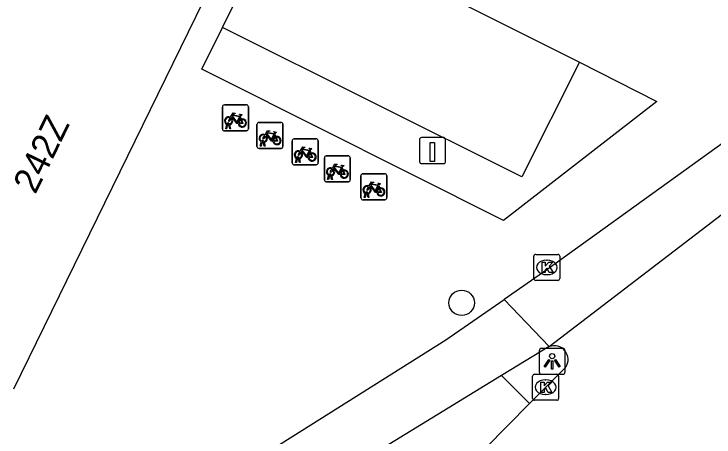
# Model space of a CAD drawing. Extents: x 160107 to 160928, y 382056 to 382918.
# Drawn here: x 160344.92 to 160371.87, y 382084.96 to 382101.23 of the extents above; entities that cross this region are included whole.
import ezdxf

# ---------------------------------------------------------------- set-up
doc = ezdxf.new("R2010")
doc.units = 0
for name, color, linetype in [('IMGEO_Boom', 7, 'Continuous'), ('IMGEO_Fietsenrek', 7, 'Continuous'), ('IMGEO_Fietspad_gesloten', 7, 'Continuous'), ('IMGEO_Kolk', 7, 'Continuous'), ('IMGEO_Laadpaal', 7, 'Continuous'), ('IMGEO_Lichtpunt', 7, 'Continuous'), ('IMGEO_Pand', 7, 'Continuous'), ('IMGEO_Pand_nummerreeks', 7, 'Continuous'), ('IMGEO_Parkeervlak_open', 7, 'Continuous'), ('IMGEO_Rijbaan_lokaal_gesloten', 7, 'Continuous'), ('IMGEO_Verkeerseiland_gesloten', 7, 'Continuous'), ('IMGEO_Voetpad_open', 7, 'Continuous')]:
    doc.layers.add(name, color=color, linetype=linetype)

msp = doc.modelspace()

# ---------------------------------------------------------------- linework, layer by layer
at = {"layer": 'IMGEO_Boom'}
msp.add_circle((160362.153, 382090.119), 0.489, dxfattribs=at)
at = {"layer": 'IMGEO_Fietsenrek'}
for p, q in [((160352.946, 382096.808), (160352.946, 382097.649)), ((160352.946, 382097.649), (160352.946, 382096.808)), ((160353.021, 382097.733), (160353.862, 382097.733)), ((160353.862, 382097.733), (160353.021, 382097.733)), ((160353.946, 382097.658), (160353.946, 382096.817)), ((160353.946, 382096.817), (160353.946, 382097.658)), ((160353.633, 382097.282), (160353.669, 382097.187)), ((160353.073, 382096.817), (160353.112, 382096.977)), ((160353.142, 382096.965), (160353.107, 382096.817)), ((160353.184, 382096.989), (160353.183, 382096.993)), ((160353.225, 382096.817), (160353.191, 382096.959)), ((160353.215, 382097), (160353.216, 382096.993)), ((160353.223, 382096.963), (160353.258, 382096.817)), ((160354.276, 382096.135), (160354.276, 382096.976)), ((160354.276, 382096.976), (160354.276, 382096.135)), ((160354.351, 382097.06), (160355.192, 382097.06)), ((160355.192, 382097.06), (160354.351, 382097.06)), ((160355.276, 382096.985), (160355.276, 382096.144)), ((160355.276, 382096.144), (160355.276, 382096.985)), ((160353.871, 382096.733), (160353.03, 382096.733)), ((160353.03, 382096.733), (160353.871, 382096.733)), ((160353.107, 382096.817), (160353.073, 382096.817)), ((160353.258, 382096.817), (160353.225, 382096.817)), ((160354.963, 382096.609), (160354.999, 382096.514)), ((160354.403, 382096.144), (160354.442, 382096.304)), ((160354.472, 382096.292), (160354.437, 382096.144)), ((160354.514, 382096.316), (160354.513, 382096.32)), ((160354.545, 382096.327), (160354.546, 382096.32)), ((160355.63, 382095.501), (160355.63, 382096.342)), ((160355.63, 382096.342), (160355.63, 382095.501)), ((160355.705, 382096.426), (160356.546, 382096.426)), ((160356.546, 382096.426), (160355.705, 382096.426)), ((160356.63, 382096.351), (160356.63, 382095.51)), ((160356.63, 382095.51), (160356.63, 382096.351)), ((160355.201, 382096.06), (160354.36, 382096.06)), ((160354.36, 382096.06), (160355.201, 382096.06)), ((160354.437, 382096.144), (160354.403, 382096.144)), ((160354.555, 382096.144), (160354.521, 382096.286)), ((160354.553, 382096.29), (160354.588, 382096.144)), ((160354.588, 382096.144), (160354.555, 382096.144)), ((160356.317, 382095.975), (160356.353, 382095.88)), ((160356.944, 382095.772), (160357.785, 382095.772)), ((160357.785, 382095.772), (160356.944, 382095.772)), ((160355.757, 382095.51), (160355.796, 382095.67)), ((160355.791, 382095.51), (160355.757, 382095.51)), ((160355.826, 382095.658), (160355.791, 382095.51)), ((160355.868, 382095.682), (160355.867, 382095.686)), ((160355.909, 382095.51), (160355.875, 382095.652)), ((160355.899, 382095.693), (160355.9, 382095.686)), ((160355.907, 382095.656), (160355.942, 382095.51)), ((160355.942, 382095.51), (160355.909, 382095.51)), ((160356.869, 382094.847), (160356.869, 382095.688)), ((160356.869, 382095.688), (160356.869, 382094.847)), ((160357.869, 382095.697), (160357.869, 382094.856)), ((160357.869, 382094.856), (160357.869, 382095.697)), ((160356.555, 382095.426), (160355.714, 382095.426)), ((160355.714, 382095.426), (160356.555, 382095.426)), ((160357.556, 382095.321), (160357.592, 382095.226)), ((160356.996, 382094.856), (160357.035, 382095.016)), ((160357.065, 382095.004), (160357.03, 382094.856)), ((160357.107, 382095.028), (160357.106, 382095.032)), ((160357.148, 382094.856), (160357.114, 382094.998)), ((160357.138, 382095.039), (160357.139, 382095.032)), ((160357.146, 382095.002), (160357.181, 382094.856)), ((160358.274, 382094.157), (160358.274, 382094.998)), ((160358.274, 382094.998), (160358.274, 382094.157)), ((160358.349, 382095.082), (160359.19, 382095.082)), ((160359.19, 382095.082), (160358.349, 382095.082)), ((160359.274, 382095.007), (160359.274, 382094.166)), ((160359.274, 382094.166), (160359.274, 382095.007)), ((160357.794, 382094.772), (160356.953, 382094.772)), ((160356.953, 382094.772), (160357.794, 382094.772)), ((160357.03, 382094.856), (160356.996, 382094.856)), ((160357.181, 382094.856), (160357.148, 382094.856)), ((160358.961, 382094.631), (160358.997, 382094.536)), ((160358.401, 382094.166), (160358.44, 382094.326)), ((160358.435, 382094.166), (160358.401, 382094.166)), ((160358.47, 382094.314), (160358.435, 382094.166)), ((160358.512, 382094.338), (160358.511, 382094.342)), ((160358.553, 382094.166), (160358.519, 382094.308)), ((160358.543, 382094.349), (160358.544, 382094.342)), ((160358.551, 382094.312), (160358.586, 382094.166)), ((160358.586, 382094.166), (160358.553, 382094.166)), ((160359.199, 382094.082), (160358.358, 382094.082)), ((160358.358, 382094.082), (160359.199, 382094.082))]:
    msp.add_line(p, q, dxfattribs=at)
for points in [[(160353.259, 382097.259), (160353.354, 382097.423), (160353.44, 382097.409), (160353.442, 382097.4), (160353.386, 382097.389), (160353.359, 382097.344), (160353.615, 382097.303)], [(160353.615, 382097.303), (160353.64, 382097.352), (160353.634, 382097.356), (160353.611, 382097.36), (160353.599, 382097.367), (160353.598, 382097.37), (160353.6, 382097.375), (160353.695, 382097.36), (160353.697, 382097.35), (160353.687, 382097.337), (160353.675, 382097.331), (160353.661, 382097.337), (160353.633, 382097.282)], [(160353.28, 382097.207), (160353.228, 382097.117), (160353.188, 382097.092), (160353.189, 382097.139), (160353.244, 382097.233)], [(160353.555, 382097.015), (160353.505, 382097.015), (160353.314, 382097.266), (160353.295, 382097.234)], [(160353.602, 382097.278), (160353.345, 382097.319), (160353.328, 382097.29), (160353.495, 382097.07), (160353.602, 382097.278)], [(160353.65, 382097.18), (160353.62, 382097.257), (160353.511, 382097.039), (160353.554, 382097.039)], [(160353.584, 382097.039), (160353.704, 382097.038), (160353.66, 382097.152)], [(160353.68, 382097.159), (160353.735, 382097.014), (160353.585, 382097.014)], [(160354.589, 382096.586), (160354.684, 382096.75), (160354.77, 382096.736), (160354.772, 382096.727), (160354.716, 382096.716), (160354.689, 382096.671), (160354.945, 382096.63)], [(160354.885, 382096.342), (160354.835, 382096.342), (160354.644, 382096.593), (160354.625, 382096.561)], [(160354.932, 382096.605), (160354.675, 382096.646), (160354.658, 382096.617), (160354.825, 382096.397), (160354.932, 382096.605)], [(160354.98, 382096.507), (160354.95, 382096.584), (160354.841, 382096.366), (160354.884, 382096.366)], [(160354.945, 382096.63), (160354.97, 382096.679), (160354.964, 382096.683), (160354.941, 382096.687), (160354.929, 382096.694), (160354.928, 382096.697), (160354.93, 382096.702), (160355.025, 382096.687), (160355.027, 382096.677), (160355.017, 382096.664), (160355.005, 382096.658), (160354.991, 382096.664), (160354.963, 382096.609)], [(160354.61, 382096.534), (160354.558, 382096.444), (160354.518, 382096.419), (160354.519, 382096.466), (160354.574, 382096.56)], [(160354.914, 382096.366), (160355.034, 382096.365), (160354.99, 382096.479)], [(160355.01, 382096.486), (160355.065, 382096.341), (160354.915, 382096.341)], [(160355.943, 382095.952), (160356.038, 382096.116), (160356.124, 382096.102), (160356.126, 382096.093), (160356.07, 382096.082), (160356.043, 382096.037), (160356.299, 382095.996)], [(160356.299, 382095.996), (160356.324, 382096.045), (160356.318, 382096.049), (160356.295, 382096.053), (160356.283, 382096.06), (160356.282, 382096.063), (160356.284, 382096.068), (160356.379, 382096.053), (160356.381, 382096.043), (160356.371, 382096.03), (160356.359, 382096.024), (160356.345, 382096.03), (160356.317, 382095.975)], [(160355.964, 382095.9), (160355.912, 382095.81), (160355.872, 382095.785), (160355.873, 382095.832), (160355.928, 382095.926)], [(160356.239, 382095.708), (160356.189, 382095.708), (160355.998, 382095.959), (160355.979, 382095.927)], [(160356.286, 382095.971), (160356.029, 382096.012), (160356.012, 382095.983), (160356.179, 382095.763), (160356.286, 382095.971)], [(160356.334, 382095.873), (160356.304, 382095.95), (160356.195, 382095.732), (160356.238, 382095.732)], [(160356.268, 382095.732), (160356.388, 382095.731), (160356.344, 382095.845)], [(160356.364, 382095.852), (160356.419, 382095.707), (160356.269, 382095.707)], [(160357.203, 382095.246), (160357.151, 382095.156), (160357.111, 382095.131), (160357.112, 382095.178), (160357.167, 382095.272)], [(160357.182, 382095.298), (160357.277, 382095.462), (160357.363, 382095.448), (160357.365, 382095.439), (160357.309, 382095.428), (160357.282, 382095.383), (160357.538, 382095.342)], [(160357.478, 382095.054), (160357.428, 382095.054), (160357.237, 382095.305), (160357.218, 382095.273)], [(160357.525, 382095.317), (160357.268, 382095.358), (160357.251, 382095.329), (160357.418, 382095.109), (160357.525, 382095.317)], [(160357.573, 382095.219), (160357.543, 382095.296), (160357.434, 382095.078), (160357.477, 382095.078)], [(160357.538, 382095.342), (160357.563, 382095.391), (160357.557, 382095.395), (160357.534, 382095.399), (160357.522, 382095.406), (160357.521, 382095.409), (160357.523, 382095.414), (160357.618, 382095.399), (160357.62, 382095.389), (160357.61, 382095.376), (160357.598, 382095.37), (160357.584, 382095.376), (160357.556, 382095.321)], [(160357.507, 382095.078), (160357.627, 382095.077), (160357.583, 382095.191)], [(160357.603, 382095.198), (160357.658, 382095.053), (160357.508, 382095.053)], [(160358.587, 382094.608), (160358.682, 382094.772), (160358.768, 382094.758), (160358.77, 382094.749), (160358.714, 382094.738), (160358.687, 382094.693), (160358.943, 382094.652)], [(160358.943, 382094.652), (160358.968, 382094.701), (160358.962, 382094.705), (160358.939, 382094.709), (160358.927, 382094.716), (160358.926, 382094.719), (160358.928, 382094.724), (160359.023, 382094.709), (160359.025, 382094.699), (160359.015, 382094.686), (160359.003, 382094.68), (160358.989, 382094.686), (160358.961, 382094.631)], [(160358.608, 382094.556), (160358.556, 382094.466), (160358.516, 382094.441), (160358.517, 382094.488), (160358.572, 382094.582)], [(160358.883, 382094.364), (160358.833, 382094.364), (160358.642, 382094.615), (160358.623, 382094.583)], [(160358.93, 382094.627), (160358.673, 382094.668), (160358.656, 382094.639), (160358.823, 382094.419), (160358.93, 382094.627)], [(160358.978, 382094.529), (160358.948, 382094.606), (160358.839, 382094.388), (160358.882, 382094.388)], [(160358.912, 382094.388), (160359.032, 382094.387), (160358.988, 382094.501)], [(160359.008, 382094.508), (160359.063, 382094.363), (160358.913, 382094.363)]]:
    msp.add_lwpolyline(points, dxfattribs=at)
for centre, radius, start, end in [((160353.024, 382097.655), 0.0779, 92.4484, 184.2845), ((160353.024, 382097.655), 0.0779, 92.4484, 184.2845), ((160353.868, 382097.655), 0.0779, 2.4484, 94.2845), ((160353.868, 382097.655), 0.0779, 2.4484, 94.2845), ((160353.186, 382097.118), 0.159, 62.6766, 242.1369), ((160353.186, 382097.118), 0.129, 63.3192, 238.903), ((160353.186, 382097.118), 0.129, 283.6043, 43.4302), ((160353.186, 382097.118), 0.159, 283.5766, 46.6042), ((160353.713, 382097.034), 0.159, 113.3408, 178.3217), ((160353.713, 382097.034), 0.159, 187.0065, 105.7708), ((160353.713, 382097.034), 0.129, 113.923, 177.9556), ((160353.713, 382097.034), 0.129, 188.6715, 104.5883), ((160353.166, 382096.989), 0.0499, 12.8025, 158.6934), ((160353.186, 382097.118), 0.159, 253.9967, 271.7867), ((160353.166, 382096.989), 0.0174, 12.8025, 163.4502), ((160353.186, 382097.118), 0.129, 253.415, 269.0204), ((160354.354, 382096.982), 0.0779, 92.4484, 184.2845), ((160354.354, 382096.982), 0.0779, 92.4484, 184.2845), ((160355.198, 382096.982), 0.0779, 2.4484, 94.2845), ((160355.198, 382096.982), 0.0779, 2.4484, 94.2845), ((160353.024, 382096.811), 0.0779, 182.4484, 274.2845), ((160353.024, 382096.811), 0.0779, 182.4484, 274.2845), ((160353.868, 382096.811), 0.0779, 272.4484, 4.2845), ((160353.868, 382096.811), 0.0779, 272.4484, 4.2845), ((160354.516, 382096.445), 0.159, 62.6766, 242.1369), ((160354.516, 382096.445), 0.129, 63.3192, 238.903), ((160354.496, 382096.316), 0.0499, 12.8025, 158.6934), ((160354.516, 382096.445), 0.159, 253.9967, 271.7867), ((160354.496, 382096.316), 0.0174, 12.8025, 163.4502), ((160354.516, 382096.445), 0.129, 253.415, 269.0204), ((160354.516, 382096.445), 0.129, 283.6043, 43.4302), ((160354.516, 382096.445), 0.159, 283.5766, 46.6042), ((160355.043, 382096.361), 0.159, 113.3408, 178.3217), ((160355.043, 382096.361), 0.159, 187.0065, 105.7708), ((160355.043, 382096.361), 0.129, 113.923, 177.9556), ((160355.043, 382096.361), 0.129, 188.6715, 104.5883), ((160355.708, 382096.348), 0.0779, 92.4484, 184.2845), ((160355.708, 382096.348), 0.0779, 92.4484, 184.2845), ((160356.552, 382096.348), 0.0779, 2.4484, 94.2845), ((160356.552, 382096.348), 0.0779, 2.4484, 94.2845), ((160354.354, 382096.138), 0.0779, 182.4484, 274.2845), ((160354.354, 382096.138), 0.0779, 182.4484, 274.2845), ((160355.198, 382096.138), 0.0779, 272.4484, 4.2845), ((160355.198, 382096.138), 0.0779, 272.4484, 4.2845), ((160355.87, 382095.811), 0.159, 62.6766, 242.1369), ((160355.87, 382095.811), 0.129, 63.3192, 238.903), ((160355.87, 382095.811), 0.129, 283.6043, 43.4302), ((160355.87, 382095.811), 0.159, 283.5766, 46.6042), ((160356.397, 382095.727), 0.159, 113.3408, 178.3217), ((160356.397, 382095.727), 0.159, 187.0065, 105.7708), ((160356.397, 382095.727), 0.129, 113.923, 177.9556), ((160356.397, 382095.727), 0.129, 188.6715, 104.5883), ((160356.947, 382095.694), 0.0779, 92.4484, 184.2845), ((160356.947, 382095.694), 0.0779, 92.4484, 184.2845), ((160357.791, 382095.694), 0.0779, 2.4484, 94.2845), ((160357.791, 382095.694), 0.0779, 2.4484, 94.2845), ((160355.708, 382095.504), 0.0779, 182.4484, 274.2845), ((160355.708, 382095.504), 0.0779, 182.4484, 274.2845), ((160355.85, 382095.682), 0.0499, 12.8025, 158.6934), ((160355.87, 382095.811), 0.159, 253.9967, 271.7867), ((160355.85, 382095.682), 0.0174, 12.8025, 163.4502), ((160355.87, 382095.811), 0.129, 253.415, 269.0204), ((160356.552, 382095.504), 0.0779, 272.4484, 4.2845), ((160356.552, 382095.504), 0.0779, 272.4484, 4.2845), ((160357.109, 382095.157), 0.159, 62.6766, 242.1369), ((160357.109, 382095.157), 0.129, 63.3192, 238.903), ((160357.109, 382095.157), 0.129, 283.6043, 43.4302), ((160357.109, 382095.157), 0.159, 283.5766, 46.6042), ((160357.636, 382095.073), 0.159, 113.3408, 178.3217), ((160357.636, 382095.073), 0.159, 187.0065, 105.7708), ((160357.089, 382095.028), 0.0499, 12.8025, 158.6934), ((160357.109, 382095.157), 0.159, 253.9967, 271.7867), ((160357.089, 382095.028), 0.0174, 12.8025, 163.4502), ((160357.109, 382095.157), 0.129, 253.415, 269.0204), ((160357.636, 382095.073), 0.129, 113.923, 177.9556), ((160357.636, 382095.073), 0.129, 188.6715, 104.5883), ((160358.352, 382095.004), 0.0779, 92.4484, 184.2845), ((160358.352, 382095.004), 0.0779, 92.4484, 184.2845), ((160359.196, 382095.004), 0.0779, 2.4484, 94.2845), ((160359.196, 382095.004), 0.0779, 2.4484, 94.2845), ((160356.947, 382094.85), 0.0779, 182.4484, 274.2845), ((160356.947, 382094.85), 0.0779, 182.4484, 274.2845), ((160357.791, 382094.85), 0.0779, 272.4484, 4.2845), ((160357.791, 382094.85), 0.0779, 272.4484, 4.2845), ((160358.514, 382094.467), 0.159, 62.6766, 242.1369), ((160358.514, 382094.467), 0.129, 63.3192, 238.903), ((160358.514, 382094.467), 0.129, 283.6043, 43.4302), ((160358.514, 382094.467), 0.159, 283.5766, 46.6042), ((160359.041, 382094.383), 0.159, 113.3408, 178.3217), ((160359.041, 382094.383), 0.159, 187.0065, 105.7708), ((160359.041, 382094.383), 0.129, 113.923, 177.9556), ((160359.041, 382094.383), 0.129, 188.6715, 104.5883), ((160358.352, 382094.16), 0.0779, 182.4484, 274.2845), ((160358.352, 382094.16), 0.0779, 182.4484, 274.2845), ((160358.494, 382094.338), 0.0499, 12.8025, 158.6934), ((160358.514, 382094.467), 0.159, 253.9967, 271.7867), ((160358.494, 382094.338), 0.0174, 12.8025, 163.4502), ((160358.514, 382094.467), 0.129, 253.415, 269.0204), ((160359.196, 382094.16), 0.0779, 272.4484, 4.2845), ((160359.196, 382094.16), 0.0779, 272.4484, 4.2845)]:
    msp.add_arc(centre, radius, start, end, dxfattribs=at)
at = {"layer": 'IMGEO_Fietspad_gesloten'}
for points in [[(160349.662, 382081.225), (160361.551, 382088.699), (160363.786, 382090.244)], [(160365.528, 382088.435), (160363.693, 382087.323)], [(160363.693, 382087.323), (160354.453, 382081.67), (160350.031, 382078.883), (160349.927, 382078.817)]]:
    msp.add_lwpolyline(points, dxfattribs=at)
at = {"layer": 'IMGEO_Kolk'}
for p, q in [((160365.005, 382091.982), (160365.857, 382091.982)), ((160364.93, 382091.056), (160364.93, 382091.908)), ((160365.418, 382091.762), (160365.443, 382091.762)), ((160365.931, 382091.908), (160365.931, 382091.056)), ((160365.441, 382091.202), (160365.416, 382091.202)), ((160365.857, 382090.982), (160365.005, 382090.982)), ((160364.886, 382086.446), (160364.886, 382087.298)), ((160364.961, 382087.372), (160365.813, 382087.372)), ((160365.374, 382087.152), (160365.399, 382087.152)), ((160365.887, 382087.298), (160365.887, 382086.446)), ((160365.813, 382086.372), (160364.961, 382086.372)), ((160365.397, 382086.592), (160365.372, 382086.592))]:
    msp.add_line(p, q, dxfattribs=at)
for points in [[(160365.005, 382091.982), (160365.857, 382091.982)], [(160364.93, 382091.056), (160364.93, 382091.908)], [(160365.931, 382091.908), (160365.931, 382091.056)], [(160365.251, 382091.682), (160365.374, 382091.682), (160365.374, 382091.531), (160365.504, 382091.682), (160365.668, 382091.682), (160365.522, 382091.531), (160365.675, 382091.282), (160365.523, 382091.282), (160365.438, 382091.446), (160365.374, 382091.379), (160365.374, 382091.282), (160365.251, 382091.282), (160365.251, 382091.682)], [(160365.857, 382090.982), (160365.005, 382090.982)], [(160364.886, 382086.446), (160364.886, 382087.298)], [(160364.961, 382087.372), (160365.813, 382087.372)], [(160365.887, 382087.298), (160365.887, 382086.446)], [(160365.207, 382087.072), (160365.33, 382087.072), (160365.33, 382086.921), (160365.46, 382087.072), (160365.624, 382087.072), (160365.478, 382086.921), (160365.631, 382086.672), (160365.479, 382086.672), (160365.394, 382086.836), (160365.33, 382086.769), (160365.33, 382086.672), (160365.207, 382086.672), (160365.207, 382087.072)], [(160365.813, 382086.372), (160364.961, 382086.372)]]:
    msp.add_lwpolyline(points, dxfattribs=at)
for centre, start, end in [((160365.007, 382091.906), 91.552, 178.448), ((160365.007, 382091.906), 91.552, 178.448), ((160365.855, 382091.906), 1.552, 88.448), ((160365.855, 382091.906), 1.552, 88.448), ((160365.007, 382091.058), 181.552, 268.448), ((160365.007, 382091.058), 181.552, 268.448), ((160365.855, 382091.058), 271.552, 358.448), ((160365.855, 382091.058), 271.552, 358.448), ((160364.963, 382087.296), 91.552, 178.448), ((160364.963, 382087.296), 91.552, 178.448), ((160365.811, 382087.296), 1.552, 88.448), ((160365.811, 382087.296), 1.552, 88.448), ((160364.963, 382086.448), 181.552, 268.448), ((160364.963, 382086.448), 181.552, 268.448), ((160365.811, 382086.448), 271.552, 358.448), ((160365.811, 382086.448), 271.552, 358.448)]:
    msp.add_arc(centre, 0.0765, start, end, dxfattribs=at)
for centre, major_axis, ratio, start_param, end_param in [((160365.417, 382091.482), (-0.387, 0.002), 0.722429, 4.712389, 7.853982), ((160365.442, 382091.482), (-0.39, 0.002), 0.717154, 1.570796, 4.712389), ((160365.373, 382086.872), (-0.387, 0.002), 0.722429, 4.712389, 7.853982), ((160365.398, 382086.872), (-0.39, 0.002), 0.717154, 1.570796, 4.712389)]:
    msp.add_ellipse(centre, major_axis=major_axis, ratio=ratio, start_param=start_param, end_param=end_param, dxfattribs=at)
at = {"layer": 'IMGEO_Laadpaal'}
for p, q in [((160360.533, 382096.392), (160360.533, 382095.551)), ((160360.533, 382096.392), (160360.533, 382095.551)), ((160361.449, 382096.476), (160360.608, 382096.476)), ((160361.449, 382096.476), (160360.608, 382096.476)), ((160361.533, 382095.56), (160361.533, 382096.401)), ((160361.533, 382095.56), (160361.533, 382096.401)), ((160360.617, 382095.476), (160361.458, 382095.476)), ((160360.617, 382095.476), (160361.458, 382095.476))]:
    msp.add_line(p, q, dxfattribs=at)
msp.add_lwpolyline([(160360.948, 382096.289), (160361.108, 382096.289), (160361.108, 382095.556), (160360.948, 382095.556), (160360.948, 382096.289)], dxfattribs=at)
for centre, start, end in [((160360.611, 382096.398), 92.4484, 184.2845), ((160360.611, 382096.398), 92.4484, 184.2845), ((160361.455, 382096.398), 2.4484, 94.2845), ((160361.455, 382096.398), 2.4484, 94.2845), ((160360.611, 382095.554), 182.4484, 274.2845), ((160360.611, 382095.554), 182.4484, 274.2845), ((160361.455, 382095.554), 272.4484, 4.2845), ((160361.455, 382095.554), 272.4484, 4.2845)]:
    msp.add_arc(centre, 0.0779, start, end, dxfattribs=at)
at = {"layer": 'IMGEO_Lichtpunt'}
for p, q in [((160365.141, 382088.273), (160365.141, 382087.466)), ((160365.141, 382088.273), (160365.141, 382087.466)), ((160366.043, 382088.368), (160365.235, 382088.368)), ((160366.043, 382088.368), (160365.235, 382088.368)), ((160366.137, 382087.466), (160366.137, 382088.273)), ((160366.137, 382087.466), (160366.137, 382088.273)), ((160365.235, 382087.372), (160366.043, 382087.372)), ((160365.235, 382087.372), (160366.043, 382087.372))]:
    msp.add_line(p, q, dxfattribs=at)
for points in [[(160365.515, 382087.937), (160365.554, 382087.909), (160365.366, 382087.647), (160365.328, 382087.674), (160365.515, 382087.937)], [(160365.617, 382087.889), (160365.664, 382087.889), (160365.664, 382087.567), (160365.617, 382087.567), (160365.617, 382087.889)], [(160365.727, 382087.909), (160365.765, 382087.936), (160365.952, 382087.674), (160365.913, 382087.646), (160365.727, 382087.909)]]:
    msp.add_lwpolyline(points, dxfattribs=at)
msp.add_circle((160365.64, 382088.071), 0.0994, dxfattribs=at)
for centre, start, end in [((160365.235, 382088.273), 90, 180), ((160365.235, 382088.273), 90, 180), ((160366.043, 382088.273), 0, 90), ((160366.043, 382088.273), 0, 90), ((160365.235, 382087.466), 180, 270), ((160365.235, 382087.466), 180, 270), ((160366.043, 382087.466), 270, 0), ((160366.043, 382087.466), 270, 360)]:
    msp.add_arc(centre, 0.0946, start, end, dxfattribs=at)
at = {"layer": 'IMGEO_Pand'}
msp.add_lwpolyline([(160352.794, 382102.932), (160344.903, 382086.804)], dxfattribs=at)
at = {"layer": 'IMGEO_Parkeervlak_open'}
msp.add_lwpolyline([(160366.685, 382099.369), (160364.467, 382094.965), (160352.952, 382100.702)], dxfattribs=at)
at = {"layer": 'IMGEO_Rijbaan_lokaal_gesloten'}
for points in [[(160388.404, 382109.546), (160382.002, 382103.966), (160373.822, 382097.426), (160365.435, 382091.385), (160363.786, 382090.244)], [(160365.528, 382088.435), (160372.418, 382093.703), (160381.834, 382101.318)], [(160363.786, 382090.244), (160365.528, 382088.435)], [(160366.166, 382087.647), (160364.77, 382086.246)], [(160364.77, 382086.246), (160355.443, 382076.784), (160354.65, 382076.013)]]:
    msp.add_lwpolyline(points, dxfattribs=at)
msp.add_arc((160365.716, 382087.935), 0.534, 327.3816, 110.6087, dxfattribs=at)
at = {"layer": 'IMGEO_Verkeerseiland_gesloten'}
msp.add_lwpolyline([(160363.693, 382087.323), (160364.77, 382086.246)], dxfattribs=at)
at = {"layer": 'IMGEO_Voetpad_open'}
for points in [[(160352.952, 382100.702), (160355.137, 382105.156), (160366.685, 382099.369)], [(160366.685, 382099.369), (160369.668, 382097.867), (160363.759, 382093.29), (160352.921, 382098.723), (160352.147, 382099.111), (160352.952, 382100.702)]]:
    msp.add_lwpolyline(points, dxfattribs=at)

# ---------------------------------------------------------------- texts
at = {"layer": 'IMGEO_Pand_nummerreeks'}
msp.add_text('242Z', height=1, rotation=63.9287, dxfattribs=at).set_placement((160345.747, 382094.263))

doc.saveas('drawing.dxf')
